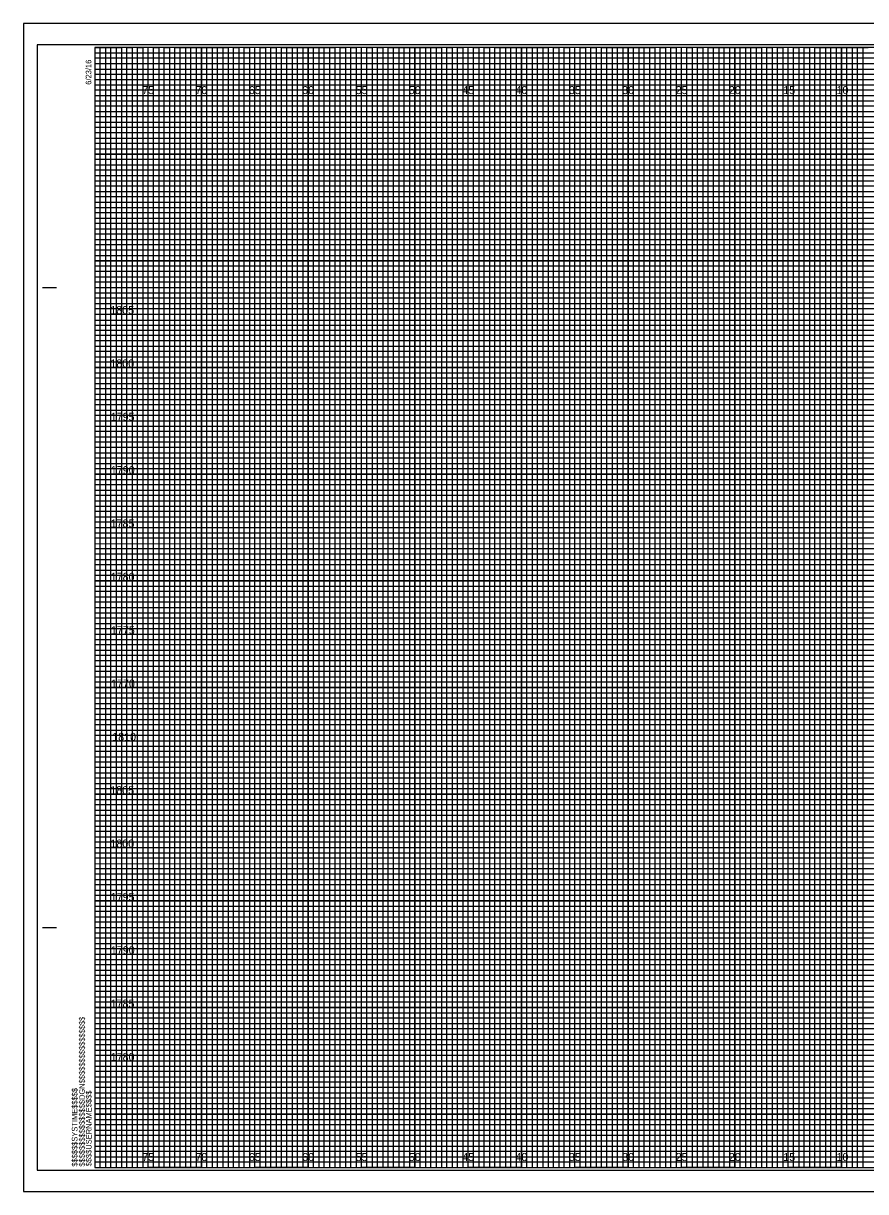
# Model space of a CAD drawing. Extents: x -7 to 162, y -2 to 217.
# Drawn here: x -6.7 to 72.2, y 107.7 to 217.2 of the extents above; entities that cross this region are included whole.
import ezdxf

# ---------------------------------------------------------------- set-up
doc = ezdxf.new("R2010")
doc.units = 0
for name, color, linetype in [('Raster_Level_0', 7, 'Continuous'), ('Scratch_Level_3', 7, 'Continuous'), ('Sheet Cross Section CELL', 7, 'Continuous'), ('Sheet Cross Section Grid Major CELL', 7, 'Continuous'), ('Sheet Cross Section Grid Middle CELL', 7, 'Continuous'), ('Sheet Cross Section Grid Minor 1 CELL', 7, 'Continuous'), ('Sheet Cross Section Grid Minor 2 CELL', 7, 'Continuous'), ('Sheet Cutting Line CELL', 7, 'Continuous'), ('Sheet DOT Grid CELL', 7, 'Continuous'), ('Sheet Plot Border Inside CELL', 7, 'Continuous'), ('Sheet Plot Border Outside CELL', 7, 'Continuous')]:
    doc.layers.add(name, color=color, linetype=linetype)

msp = doc.modelspace()

# ---------------------------------------------------------------- linework, layer by layer
at = {"layer": 'Sheet Cross Section CELL'}
for p, q in [((-4.9, 192.5), (-3.65, 192.5)), ((-4.85, 192.5), (-3.6, 192.5)), ((-4.9, 132.5), (-3.65, 132.5)), ((-4.85, 132.5), (-3.6, 132.5)), ((0, 110), (0, 110)), ((0, 110), (0, 110)), ((0, 110), (0, 110)), ((0, 110), (0, 110)), ((0, 110), (0, 110)), ((0, 110), (0, 110)), ((0, 110), (0, 110))]:
    msp.add_line(p, q, dxfattribs=at)
msp.add_lwpolyline([(160, 215), (0, 215), (0, 110), (160, 110)], close=True, dxfattribs=at)
at = {"layer": 'Sheet Cross Section Grid Major CELL'}
for p, q in [((5, 215), (0, 215)), ((5, 110), (5, 215)), ((15, 215), (10, 215)), ((10, 215), (10, 110)), ((15, 110), (15, 215)), ((25, 215), (20, 215)), ((20, 215), (20, 110)), ((25, 110), (25, 215)), ((35, 215), (30, 215)), ((30, 215), (30, 110)), ((35, 110), (35, 215)), ((45, 215), (40, 215)), ((40, 215), (40, 110)), ((45, 110), (45, 215)), ((55, 215), (50, 215)), ((50, 215), (50, 110)), ((55, 110), (55, 215)), ((65, 215), (60, 215)), ((60, 215), (60, 110)), ((65, 110), (65, 215)), ((75, 215), (70, 215)), ((70, 215), (70, 110)), ((10, 110), (5, 110)), ((20, 110), (15, 110)), ((30, 110), (25, 110)), ((40, 110), (35, 110)), ((50, 110), (45, 110)), ((60, 110), (55, 110)), ((70, 110), (65, 110))]:
    msp.add_line(p, q, dxfattribs=at)
for points in [[(0, 210), (160, 210), (160, 205), (0, 205)], [(0, 200), (160, 200), (160, 195), (0, 195)], [(0, 190), (160, 190), (160, 185), (0, 185)], [(0, 180), (160, 180), (160, 175), (0, 175)], [(0, 170), (160, 170), (160, 165), (0, 165)], [(0, 160), (160, 160), (160, 155), (0, 155)], [(0, 150), (160, 150), (160, 145), (0, 145)], [(0, 140), (160, 140), (160, 135), (0, 135)], [(0, 130), (160, 130), (160, 125), (0, 125)], [(0, 120), (160, 120), (160, 115), (0, 115)]]:
    msp.add_lwpolyline(points, dxfattribs=at)
at = {"layer": 'Sheet Cross Section Grid Middle CELL'}
for points in [[(0, 215), (2.5, 215), (2.5, 110), (7.5, 110), (7.5, 215), (12.5, 215), (12.5, 110), (17.5, 110), (17.5, 215), (22.5, 215), (22.5, 110), (27.5, 110), (27.5, 215), (32.5, 215), (32.5, 110), (37.5, 110), (37.5, 215), (42.5, 215), (42.5, 110), (47.5, 110), (47.5, 215), (52.5, 215), (52.5, 110), (57.5, 110), (57.5, 215), (62.5, 215), (62.5, 110), (67.5, 110), (67.5, 215), (72.5, 215)], [(0, 212.5), (137.5, 212.5)], [(0, 202.5), (160, 202.5), (160, 207.5), (0, 207.5)], [(0, 192.5), (160, 192.5), (160, 197.5), (0, 197.5)], [(0, 182.5), (160, 182.5), (160, 187.5), (0, 187.5)], [(0, 172.5), (160, 172.5), (160, 177.5), (0, 177.5)], [(0, 162.5), (160, 162.5), (160, 167.5), (0, 167.5)], [(0, 152.5), (160, 152.5), (160, 157.5), (0, 157.5)], [(0, 142.5), (160, 142.5), (160, 147.5), (0, 147.5)], [(0, 132.5), (160, 132.5), (160, 137.5), (0, 137.5)], [(0, 122.5), (160, 122.5), (160, 127.5), (0, 127.5)], [(0, 112.5), (160, 112.5), (160, 117.5), (0, 117.5)]]:
    msp.add_lwpolyline(points, dxfattribs=at)
at = {"layer": 'Sheet Cross Section Grid Minor 1 CELL'}
for p, q in [((0, 214.5), (130, 214.5)), ((130, 213.99), (0, 213.99)), ((0, 213.99), (0, 213.5)), ((0, 213.5), (130, 213.5)), ((130, 212.94), (0, 212.94)), ((0, 212.94), (0, 212)), ((0, 212), (160, 212))]:
    msp.add_line(p, q, dxfattribs=at)
for points in [[(0, 211.5), (135, 211.5), (160, 211.5), (160, 211), (0, 211)], [(0, 210.5), (160, 210.5), (160, 209.5), (0, 209.5)], [(0, 209), (160, 209), (160, 208.5), (0, 208.49)], [(0, 208), (160, 208), (160, 207), (0, 207)], [(0, 206.5), (160, 206.5), (160, 206), (0, 206)], [(0, 205.5), (160, 205.5), (160, 204.5), (0, 204.5)], [(0, 204), (160, 204), (160, 203.5), (0, 203.5)], [(0, 203), (160, 203), (160, 202), (0, 202)], [(0, 201.5), (160, 201.5), (160, 201), (0, 201)], [(0, 200.5), (160, 200.5), (160, 199.5), (0, 199.5)], [(0, 199), (160, 199), (160, 198.5), (0, 198.5)], [(0, 198), (160, 198), (160, 196.97), (160, 196.5), (160, 196), (0, 196)], [(0, 197), (160, 197), (160, 196.5), (0, 196.5)], [(0, 195.5), (160, 195.5), (160, 194.5), (0, 194.52)], [(0, 194.52), (160, 194.5), (160, 194), (0, 194)], [(0, 193.5), (160, 193.5), (160, 193), (0, 193)], [(0, 192), (160, 192), (160, 191.5), (0, 191.5)], [(0, 191), (160, 191), (160, 190.5), (0, 190.5)], [(-0.04, 189.44), (160, 189.44), (160, 188.94), (-0.04, 188.94)], [(0, 188.5), (160, 188.5), (160, 188), (0, 188)], [(0, 187), (160, 187), (160, 186.5), (0, 186.5)], [(0, 186), (160, 186), (160, 185.5), (0, 185.5)], [(0, 184.5), (160, 184.5), (160, 184), (0, 184)], [(0, 183.5), (160, 183.5), (160, 183), (0, 183)], [(0, 182), (160, 182), (160, 181.5), (0, 181.5)], [(0, 181), (160, 181), (160, 180.5), (0, 180.5)], [(0, 179.5), (160, 179.5), (160, 178.99), (0, 179)], [(0, 178.5), (160, 178.5), (160, 178), (0, 178)], [(0, 177), (160, 177), (160, 176.5), (0, 176.5)], [(0, 176), (160, 176), (160, 175.5), (0, 175.5)], [(0, 174.5), (160, 174.5), (160, 174), (0, 174)], [(0, 173.5), (160, 173.5), (160, 173), (0, 173)], [(0, 172), (160, 172), (160, 171.5), (0, 171.5)], [(0, 171), (160, 171), (160, 170.5), (0, 170.5)], [(0, 169.5), (160, 169.5), (160, 169), (0, 169)], [(0, 168.5), (160.03, 168.46), (160, 168), (0, 168)], [(0, 167), (160, 167), (160, 166.5), (0, 166.5)], [(0, 166), (160, 166), (160, 165.5), (0, 165.5)], [(0, 164.5), (160, 164.5), (160, 164), (0, 164)], [(0, 163.5), (160, 163.5), (160, 163), (0, 163)], [(0, 162), (160, 162), (160, 161.5), (0, 161.5)], [(0, 161), (160, 161), (160, 160.5), (0, 160.5)], [(0, 159.5), (160, 159.5), (160, 159), (0, 159)], [(0, 158.5), (160, 158.5), (160, 158), (0, 158)], [(0, 157), (160, 157), (160, 156.5), (0, 156.5)], [(0, 156), (160, 156), (160, 155.5), (0, 155.5)], [(0, 154.5), (160, 154.5), (160, 154), (0, 154)], [(0, 153.5), (160, 153.5), (160, 153), (0, 153)], [(0, 152), (160, 152), (160, 151.5), (0, 151.5)], [(0, 151), (160, 151), (160, 150.5), (0, 150.5)], [(0, 149.5), (160, 149.5), (160, 148.99), (0, 149)], [(0, 148.5), (160, 148.5), (160, 148), (0, 148)], [(0, 147), (160, 147), (160, 146.5), (0, 146.5)], [(0, 146), (160, 146), (160, 145.5), (0, 145.5)], [(0, 144.5), (160, 144.5), (160, 144), (0, 144)], [(0, 143.5), (160, 143.5), (160, 143), (0, 143)], [(0, 142), (160, 142), (160, 141.5), (0, 141.5)], [(0, 141), (160, 141), (160, 140.5), (0, 140.5)], [(0, 139.5), (160, 139.5), (160, 139), (0, 139)], [(0, 138.5), (160.03, 138.46), (160, 138), (0, 138)], [(0, 137), (160, 137), (160, 136.5), (0, 136.5)], [(0, 136), (160, 136), (160, 135.5), (0, 135.5)], [(0, 134.5), (160, 134.5), (160, 134), (0, 134)], [(0, 133.5), (160, 133.5), (160, 133), (0, 133)], [(0, 132), (160, 132), (160, 131.5), (0, 131.5)], [(0, 131), (160, 131), (160, 130.5), (0, 130.5)], [(0, 129.5), (160, 129.5), (160, 129), (0, 129)], [(0, 128.5), (160, 128.5), (160, 128), (0, 128)], [(0, 127), (160, 127), (160, 126.5), (0, 126.5)], [(0, 126), (160, 126), (160, 125.5), (0, 125.5)], [(0, 124.5), (160, 124.5), (160, 124), (0, 124)], [(0, 123.5), (160, 123.5), (160, 123), (0, 123)], [(0, 122), (160, 122), (160, 121.5), (0, 121.5)], [(0, 121), (160, 121), (160, 120.5), (0, 120.5)], [(0, 119.5), (160, 119.5), (160, 119), (0, 119)], [(0, 118.5), (160, 118.5), (160, 118), (0, 118)], [(0, 117), (160, 117), (160, 116.5), (0, 116.5)], [(0, 116), (160, 116), (160, 115.5), (0, 115.5)], [(0, 114.5), (160, 114.5), (160, 114), (0, 114)], [(0, 113.5), (160, 113.5), (160, 113), (0, 113)], [(0, 112), (160, 112), (160, 111.5), (0, 111.5)], [(0, 111), (160, 111), (160, 110.5), (0, 110.5)]]:
    msp.add_lwpolyline(points, dxfattribs=at)
at = {"layer": 'Sheet Cross Section Grid Minor 2 CELL'}
for points in [[(0, 110), (0.5, 110), (0.5, 215), (1, 215), (1, 110)], [(1, 110), (1.5, 110), (1.5, 215), (2, 215), (2, 110)], [(2.5, 110), (3, 110), (3, 215), (3.5, 215), (3.5, 110)], [(3.5, 110), (4, 110), (4, 215), (4.5, 215), (4.5, 110)], [(5, 110), (5.5, 110), (5.5, 215), (6, 215), (6, 110)], [(6, 110), (6.5, 110), (6.5, 215), (7, 215), (7, 110)], [(7.5, 110), (8, 110), (8, 215), (8.5, 215), (8.5, 110)], [(8.5, 110), (9, 110), (9, 215), (9.5, 215), (9.5, 110)], [(10, 110), (10.5, 110), (10.5, 215), (11, 215), (11, 110)], [(11, 110), (11.5, 110), (11.5, 215), (12, 215), (12, 110)], [(12.5, 110), (13, 110), (13, 215), (13.5, 215), (13.5, 110)], [(13.5, 110), (14, 110), (14, 215), (14.5, 215), (14.5, 110)], [(15, 110), (15.5, 110), (15.5, 215), (16, 215), (16, 110)], [(16, 110), (16.5, 110), (16.5, 215), (17, 215), (17, 110)], [(17.5, 110), (18, 110), (18, 215), (18.5, 215), (18.5, 110)], [(18.5, 110), (19, 110), (19, 215), (19.5, 215), (19.5, 110)], [(20, 110), (20.5, 110), (20.5, 215), (21, 215), (21, 110)], [(21, 110), (21.5, 110), (21.5, 215), (22, 215), (22, 110)], [(22.5, 110), (23, 110), (23, 215), (23.5, 215), (23.5, 110)], [(23.5, 110), (24, 110), (24, 215), (24.5, 215), (24.5, 110)], [(25, 110), (25.5, 110), (25.5, 215), (26, 215), (26, 110)], [(26, 110), (26.5, 110), (26.5, 215), (27, 215), (27, 110)], [(27.5, 110), (28, 110), (28, 215), (28.5, 215), (28.5, 110)], [(28.5, 110), (29, 110), (29, 215), (29.5, 215), (29.5, 110)], [(30, 110), (30.5, 110), (30.5, 215), (31, 215), (31, 110)], [(31, 110), (31.5, 110), (31.5, 215), (32, 215), (32, 110)], [(32.5, 110), (33, 110), (33, 215), (33.5, 215), (33.5, 110)], [(33.5, 110), (34, 110), (34, 215), (34.5, 215), (34.5, 110)], [(35, 110), (35.5, 110), (35.5, 215), (36, 215), (36, 110)], [(36, 110), (36.5, 110), (36.5, 215), (37, 215), (37, 110)], [(37.5, 110), (38, 110), (38, 215), (38.5, 215), (38.5, 110)], [(38.5, 110), (39, 110), (39, 215), (39.5, 215), (39.5, 110)], [(40, 110), (40.5, 110), (40.5, 215), (41, 215), (41, 110)], [(41, 110), (41.5, 110), (41.5, 215), (42, 215), (42, 110)], [(42.5, 110), (43, 110), (43, 215), (43.5, 215), (43.5, 110)], [(43.5, 110), (44, 110), (44, 215), (44.5, 215), (44.5, 110)], [(45, 110), (45.5, 110), (45.5, 215), (46, 215), (46, 110)], [(46, 110), (46.5, 110), (46.5, 215), (47, 215), (47, 110)], [(47.5, 110), (48, 110), (48, 215), (48.5, 215), (48.5, 110)], [(48.5, 110), (49, 110), (49, 215), (49.5, 215), (49.5, 110)], [(50, 110), (50.5, 110), (50.5, 215), (51, 215), (51, 110)], [(51, 110), (51.5, 110), (51.5, 215), (52, 215), (52, 110)], [(52.5, 110), (53, 110), (53, 215), (53.5, 215), (53.5, 110)], [(53.5, 110), (54, 110), (54, 215), (54.5, 215), (54.5, 110)], [(55, 110), (55.5, 110), (55.5, 215), (56, 215), (56, 110)], [(56, 110), (56.5, 110), (56.5, 215), (57, 215), (57, 110)], [(57.5, 110), (58, 110), (58, 215), (58.5, 215), (58.5, 110)], [(58.5, 110), (59, 110), (59, 215), (59.5, 215), (59.5, 110)], [(60, 110), (60.5, 110), (60.5, 215), (61, 215), (61, 110)], [(61, 110), (61.5, 110), (61.5, 215), (62, 215), (62, 110)], [(62.5, 110), (63, 110), (63, 215), (63.5, 215), (63.5, 110)], [(63.5, 110), (64, 110), (64, 215), (64.5, 215), (64.5, 110)], [(65, 110), (65.5, 110), (65.5, 215), (66, 215), (66, 110)], [(66, 110), (66.5, 110), (66.5, 215), (67, 215), (67, 110)], [(67.5, 110), (68, 110), (68, 215), (68.5, 215), (68.5, 110)], [(68.5, 110), (69, 110), (69, 215), (69.5, 215), (69.5, 110)], [(70, 110), (70.5, 110), (70.5, 215), (71, 215), (71, 110)], [(71, 110), (71.5, 110), (71.5, 215), (72, 215), (72, 110)]]:
    msp.add_lwpolyline(points, dxfattribs=at)
at = {"layer": 'Sheet Cutting Line CELL'}
for p, q in [((161.65, 217.25), (-6.7, 217.25)), ((-6.7, 217.25), (-6.7, 107.75)), ((-6.7, 107.75), (161.65, 107.75))]:
    msp.add_line(p, q, dxfattribs=at)
at = {"layer": 'Sheet DOT Grid CELL'}
for p, q in [((5, 110), (5, 215)), ((10, 110), (10, 215)), ((15, 110), (15, 215)), ((20, 110), (20, 215)), ((25, 110), (25, 215)), ((30, 110), (30, 215)), ((35, 110), (35, 215)), ((40, 110), (40, 215)), ((45, 110), (45, 215)), ((50, 110), (50, 215)), ((55, 110), (55, 215)), ((60, 110), (60, 215)), ((65, 110), (65, 215)), ((70, 110), (70, 215)), ((0, 210), (160, 210)), ((0, 205), (160, 205)), ((0, 200), (160, 200)), ((0, 195), (160, 195)), ((0, 190), (160, 190)), ((0, 185), (160, 185)), ((0, 180), (160, 180)), ((0, 175), (160, 175)), ((0, 170), (160, 170)), ((0, 165), (160, 165)), ((0, 160), (160, 160)), ((0, 155), (160, 155)), ((0, 150), (160, 150)), ((0, 145), (160, 145)), ((0, 140), (160, 140)), ((0, 135), (160, 135)), ((0, 130), (160, 130)), ((0, 125), (160, 125)), ((0, 120), (160, 120)), ((0, 115), (160, 115))]:
    msp.add_line(p, q, dxfattribs=at)
at = {"layer": 'Sheet Plot Border Inside CELL'}
msp.add_lwpolyline([(-5.4, 109.75), (161.2, 109.75), (161.2, 215.25), (-5.4, 215.25)], close=True, dxfattribs=at)
at = {"layer": 'Sheet Plot Border Outside CELL'}
msp.add_lwpolyline([(-6.7, 107.75), (161.65, 107.75), (161.65, 217.25), (-6.7, 217.25)], close=True, dxfattribs=at)

# ---------------------------------------------------------------- texts
at = {"layer": 'Raster_Level_0'}
for s, p in [('75', (4.44, 210.62)), ('70', (9.43, 210.62)), ('65', (14.44, 210.62)), ('60', (19.43, 210.62)), ('55', (24.44, 210.62)), ('50', (29.43, 210.62)), ('45', (34.44, 210.62)), ('40', (39.43, 210.62)), ('35', (44.44, 210.62)), ('30', (49.43, 210.62)), ('25', (54.44, 210.62)), ('20', (59.43, 210.62)), ('15', (64.53, 210.62)), ('10', (69.52, 210.62)), ('75', (4.44, 110.62)), ('70', (9.43, 110.62)), ('65', (14.44, 110.62)), ('60', (19.43, 110.62)), ('55', (24.44, 110.62)), ('50', (29.43, 110.62)), ('45', (34.44, 110.62)), ('40', (39.43, 110.62)), ('35', (44.44, 110.62)), ('30', (49.43, 110.62)), ('25', (54.44, 110.62)), ('20', (59.43, 110.62)), ('15', (64.53, 110.62)), ('10', (69.52, 110.62))]:
    msp.add_text(s, height=0.75, dxfattribs=at).set_placement(p)
at = {"layer": 'Scratch_Level_3'}
for s, p in [('1805', (1.45, 190)), ('1800', (1.46, 185)), ('1795', (1.49, 180)), ('1790', (1.5, 175)), ('1785', (1.48, 170)), ('1780', (1.49, 165)), ('1775', (1.51, 160)), ('1770', (1.52, 155)), ('1810', (1.63, 150)), ('1805', (1.45, 145)), ('1800', (1.46, 140)), ('1795', (1.49, 135)), ('1790', (1.5, 130)), ('1785', (1.48, 125)), ('1780', (1.49, 120))]:
    msp.add_text(s, height=0.75, dxfattribs=at).set_placement(p)
at = {"layer": 'Sheet Cross Section CELL'}
for s, p in [('6/23/16', (-0.33, 211.5)), ('$$$$$$$$$$$$$$$$DGN$$$$$$$$$$$$$$$$', (-0.94, 110.09)), ('$$$$$$SYSTIME$$$$$', (-1.63, 110.09)), ('$$$$USERNAME$$$$', (-0.31, 110.12))]:
    msp.add_text(s, height=0.525, rotation=90, dxfattribs=at).set_placement(p)

doc.saveas('drawing.dxf')
